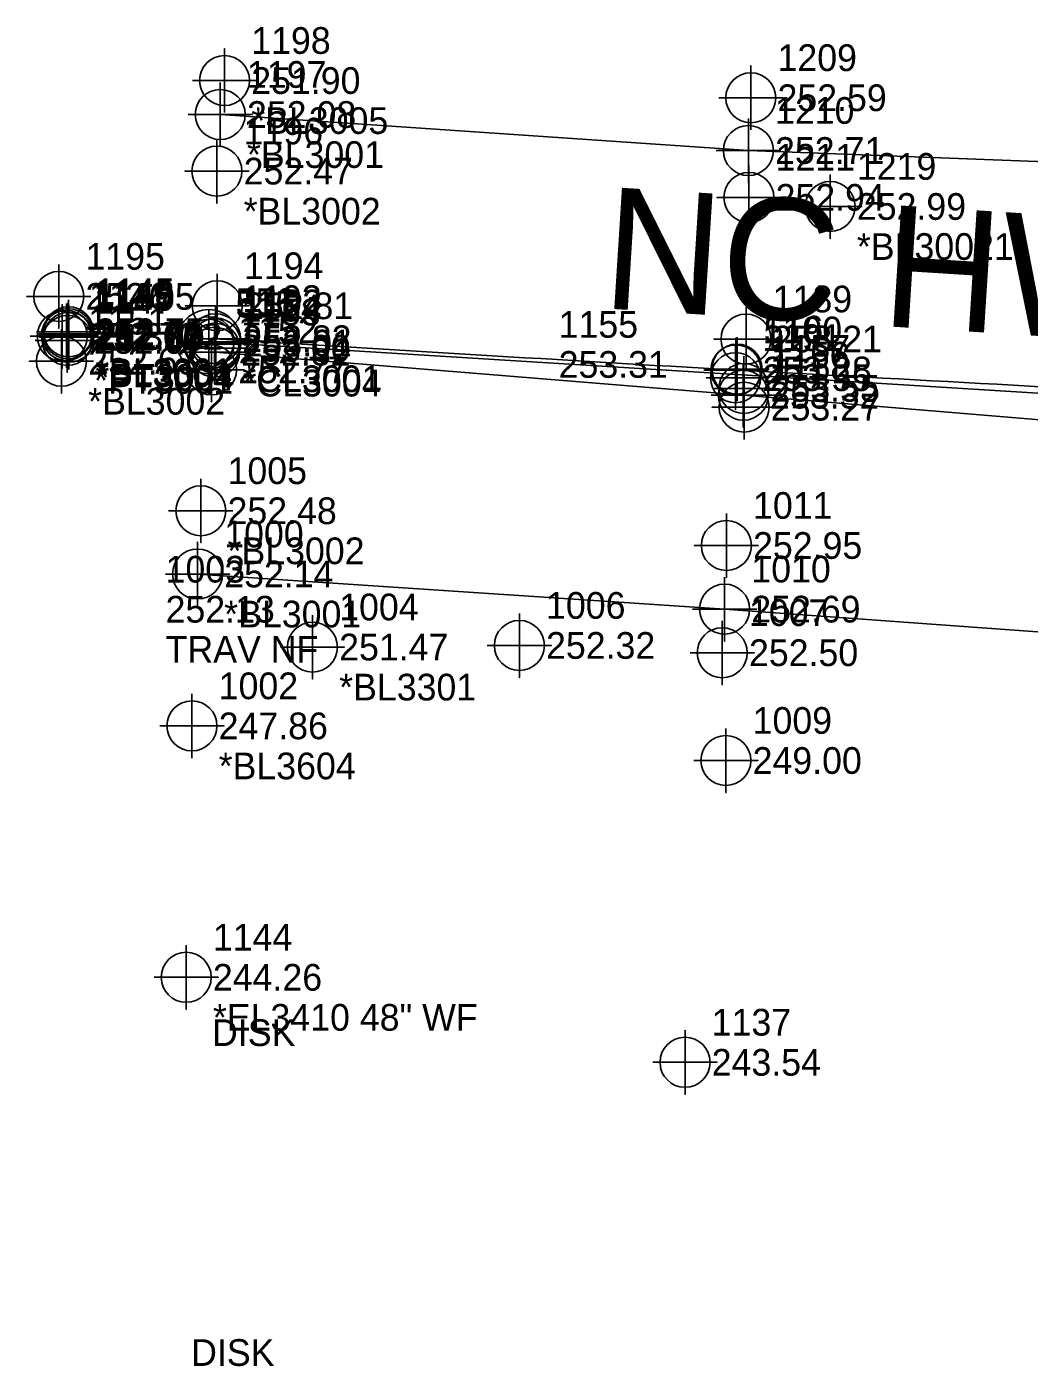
# Model space of a CAD drawing. Extents: x 2130621 to 2131998, y 642516 to 644503.
# Drawn here: x 2130981.3 to 2131075.1, y 643098.3 to 643223.7 of the extents above; entities that cross this region are included whole.
import ezdxf

# ---------------------------------------------------------------- set-up
doc = ezdxf.new("R2010")
doc.units = 0
for name, color, linetype in [('Cogo Default Point CELL', 7, 'Continuous'), ('COGO Default Point Number', 7, 'Continuous'), ('CTL Secondary Horizontal and Vertical Cogo Comment', 7, 'Continuous'), ('CTL Secondary Horizontal and Vertical Cogo Elevation', 7, 'Continuous'), ('CTL Secondary Horizontal and Vertical Cogo Number', 7, 'Continuous'), ('Exist Guardrail Cogo Comment', 7, 'Continuous'), ('Exist Guardrail Cogo Elevation', 7, 'Continuous'), ('Exist Guardrail Cogo Number', 7, 'Continuous'), ('Exist Guardrail Cogo Point CELL', 7, 'Continuous'), ('Exist Other Culture Fence Line Cogo Comment', 7, 'Continuous'), ('Exist Other Culture Fence Line Cogo Elevation', 7, 'Continuous'), ('Exist Other Culture Fence Line Cogo Number', 7, 'Continuous'), ('Exist Other Culture Fence Line Cogo Point CELL', 7, 'Continuous'), ('Exist Other Culture Sign Cogo Elevation', 7, 'Continuous'), ('Exist Other Culture Sign Cogo Number', 7, 'Continuous'), ('Exist Right of Way Monument Cogo Comment', 7, 'Continuous'), ('Exist Roads Curbs Cogo Comment', 7, 'Continuous'), ('Exist Roads Curbs Cogo Elevation', 7, 'Continuous'), ('Exist Roads Curbs Cogo Number', 7, 'Continuous'), ('Exist Roads Curbs Cogo Point CELL', 7, 'Continuous'), ('Exist Roads EOP', 7, 'Continuous'), ('Exist Roads EOP Cogo Comment', 7, 'Continuous'), ('Exist Roads EOP Cogo Elevation', 7, 'Continuous'), ('Exist Roads EOP Cogo Number', 7, 'Continuous'), ('Exist Roads EOP Cogo Point CELL', 7, 'Continuous'), ('Exist Roads EOT Cogo Comment', 7, 'Continuous'), ('Exist Roads EOT Cogo Elevation', 7, 'Continuous'), ('Exist Roads EOT Cogo Number', 7, 'Continuous'), ('Exist Roads EOT Cogo Point CELL', 7, 'Continuous'), ('Exist Roads EOT Text', 7, 'Continuous'), ('Exist Roads Soil Cogo Comment', 7, 'Continuous'), ('Exist Roads Soil Cogo Elevation', 7, 'Continuous'), ('Exist Roads Soil Cogo Number', 7, 'Continuous'), ('Exist Roads Soil Cogo Point CELL', 7, 'Continuous'), ('Exist Vegetation Woods Line Cogo Comment', 7, 'Continuous'), ('Exist Vegetation Woods Line Cogo Elevation', 7, 'Continuous'), ('Exist Vegetation Woods Line Cogo Number', 7, 'Continuous'), ('Exist Vegetation Woods Line Cogo Point CELL', 7, 'Continuous'), ('Prop Horizontal Alignment', 7, 'Continuous')]:
    doc.layers.add(name, color=color, linetype=linetype)

msp = doc.modelspace()

# ---------------------------------------------------------------- linework, layer by layer
at = {"layer": 'Cogo Default Point CELL'}
for points in [[(2130998.32, 643197.18), (2130998.32, 643194.18)], [(2130998.32, 643196.94), (2130998.32, 643193.94)], [(2130995.32, 643194.18), (2130998.32, 643194.18)], [(2130995.32, 643193.94), (2130998.32, 643193.94)], [(2130998.32, 643194.18), (2131001.32, 643194.18)], [(2130998.32, 643194.18), (2130998.32, 643191.18)], [(2130998.32, 643193.94), (2131001.32, 643193.94)], [(2130998.32, 643193.94), (2130998.32, 643190.94)], [(2131047.77, 643194.61), (2131047.77, 643191.61)], [(2131044.77, 643191.61), (2131047.77, 643191.61)], [(2131047.77, 643191.61), (2131050.77, 643191.61)], [(2131047.77, 643191.61), (2131047.77, 643188.61)]]:
    msp.add_lwpolyline(points, dxfattribs=at)
for centre in [(2130998.32, 643194.18), (2130998.32, 643193.94), (2131047.77, 643191.61)]:
    msp.add_circle(centre, 2.34, dxfattribs=at)
at = {"layer": 'Exist Guardrail Cogo Point CELL'}
for points in [[(2131008.02, 643168.59), (2131008.02, 643162.59), (2131008.02, 643165.59), (2131011.02, 643165.59), (2131005.02, 643165.59)], [(2131027.39, 643168.74), (2131027.39, 643162.74), (2131027.39, 643165.74), (2131030.39, 643165.74), (2131024.39, 643165.74)], [(2131046.39, 643168.06), (2131046.39, 643162.06), (2131046.39, 643165.06), (2131049.39, 643165.06), (2131043.39, 643165.06)]]:
    msp.add_lwpolyline(points, dxfattribs=at)
for centre in [(2131008.02, 643165.59), (2131027.39, 643165.74), (2131046.39, 643165.06)]:
    msp.add_circle(centre, 2.34, dxfattribs=at)
at = {"layer": 'Exist Other Culture Fence Line Cogo Point CELL'}
for points in [[(2130996.2, 643137.67), (2130996.2, 643131.67), (2130996.2, 643134.67), (2130999.2, 643134.67), (2130993.2, 643134.67)], [(2131042.9, 643129.71), (2131042.9, 643123.71), (2131042.9, 643126.71), (2131045.9, 643126.71), (2131039.9, 643126.71)]]:
    msp.add_lwpolyline(points, dxfattribs=at)
for centre in [(2130996.2, 643134.67), (2131042.9, 643126.71)]:
    msp.add_circle(centre, 2.34, dxfattribs=at)
at = {"layer": 'Exist Roads Curbs Cogo Point CELL'}
for points in [[(2130984.98, 643197.77), (2130984.98, 643191.77), (2130984.98, 643194.77), (2130982.25, 643194.77), (2130987.98, 643194.77)], [(2130985.16, 643197.92), (2130985.16, 643191.92), (2130985.16, 643194.92), (2130982.43, 643194.92), (2130988.16, 643194.92)], [(2130985.2, 643197.59), (2130985.2, 643191.59), (2130985.2, 643194.59), (2130982.47, 643194.59), (2130988.2, 643194.59)], [(2130998.87, 643196.57), (2130998.87, 643190.57), (2130998.87, 643193.57), (2130996.14, 643193.57), (2131001.87, 643193.57)], [(2130998.98, 643197.05), (2130998.98, 643191.05), (2130998.98, 643194.05), (2130996.25, 643194.05), (2131001.98, 643194.05)], [(2131047.63, 643193.81), (2131047.63, 643187.81), (2131047.63, 643190.81), (2131044.9, 643190.81), (2131050.63, 643190.81)], [(2131048.41, 643192.81), (2131048.41, 643186.81), (2131048.41, 643189.81), (2131045.68, 643189.81), (2131051.41, 643189.81)]]:
    msp.add_lwpolyline(points, dxfattribs=at)
for centre in [(2130984.98, 643194.77), (2130985.16, 643194.92), (2130985.2, 643194.59), (2130998.98, 643194.05), (2130998.87, 643193.57), (2131047.63, 643190.81), (2131048.41, 643189.81)]:
    msp.add_circle(centre, 2.34, dxfattribs=at)
at = {"layer": 'Exist Roads EOP'}
msp.add_line((2130998.95, 643194.46), (2131003.83, 643194.23), dxfattribs=at)
for points in [[(2130999.39, 643215.45), (2131048.83, 643212.08), (2131098.77, 643210.18), (2131123.48, 643210.52)], [(2130999.32, 643193.17), (2131048.36, 643189.17), (2131096.04, 643185.22), (2131148.03, 643181.19), (2131197.86, 643177.88), (2131226.61, 643175.76)], [(2130997.26, 643172.43), (2131046.61, 643169.14), (2131095.28, 643165.62), (2131146.45, 643162.12), (2131188.44, 643158.22), (2131196.4, 643155.89)]]:
    msp.add_lwpolyline(points, dxfattribs=at)
msp.add_spline([(2131226.91, 643179.17), (2131198.07, 643181.47), (2131148.43, 643185.15), (2131096.5, 643188.78), (2131047.67, 643191.53), (2130998.95, 643194.46)], degree=3, dxfattribs=at)
at = {"layer": 'Exist Roads EOP Cogo Point CELL'}
for points in [[(2130999.39, 643218.45), (2130999.39, 643212.45), (2130999.39, 643215.45), (2131002.39, 643215.45), (2130996.39, 643215.45)], [(2131048.83, 643215.08), (2131048.83, 643209.08), (2131048.83, 643212.08), (2131051.83, 643212.08), (2131045.83, 643212.08)], [(2130984.6, 643197.69), (2130984.6, 643191.69), (2130984.6, 643194.69), (2130987.6, 643194.69), (2130981.6, 643194.69)], [(2130985.19, 643198.11), (2130985.19, 643192.11), (2130985.19, 643195.11), (2130988.19, 643195.11), (2130982.19, 643195.11)], [(2130998.95, 643197.46), (2130998.95, 643191.46), (2130998.95, 643194.46), (2131001.95, 643194.46), (2130995.95, 643194.46)], [(2130985.07, 643197.3), (2130985.07, 643191.3), (2130985.07, 643194.3), (2130988.07, 643194.3), (2130982.07, 643194.3)], [(2130998.86, 643196.2), (2130998.86, 643190.2), (2130998.86, 643193.2), (2131001.86, 643193.2), (2130995.86, 643193.2)], [(2131047.67, 643194.53), (2131047.67, 643188.53), (2131047.67, 643191.53), (2131050.67, 643191.53), (2131044.67, 643191.53)], [(2131048.36, 643192.17), (2131048.36, 643186.17), (2131048.36, 643189.17), (2131051.36, 643189.17), (2131045.36, 643189.17)], [(2130997.26, 643175.43), (2130997.26, 643169.43), (2130997.26, 643172.43), (2131000.26, 643172.43), (2130994.26, 643172.43)], [(2131046.61, 643172.14), (2131046.61, 643166.14), (2131046.61, 643169.14), (2131049.61, 643169.14), (2131043.61, 643169.14)]]:
    msp.add_lwpolyline(points, dxfattribs=at)
for centre in [(2130999.39, 643215.45), (2131048.83, 643212.08), (2130985.19, 643195.11), (2130984.6, 643194.69), (2130985.07, 643194.3), (2130998.95, 643194.46), (2130998.86, 643193.2), (2131047.67, 643191.53), (2131048.36, 643189.17), (2130997.26, 643172.43), (2131046.61, 643169.14)]:
    msp.add_circle(centre, 2.34, dxfattribs=at)
at = {"layer": 'Exist Roads EOT Cogo Point CELL'}
for points in [[(2130999.08, 643213.15), (2130999.08, 643207.15), (2130999.08, 643210.15), (2130996.08, 643210.15), (2131002.08, 643210.15)], [(2131048.88, 643210.69), (2131048.88, 643204.69), (2131048.88, 643207.69), (2131045.88, 643207.69), (2131051.88, 643207.69)], [(2131056.49, 643209.84), (2131056.49, 643203.84), (2131056.49, 643206.84), (2131053.49, 643206.84), (2131059.49, 643206.84)], [(2130984.27, 643201.42), (2130984.27, 643195.42), (2130984.27, 643198.42), (2130981.27, 643198.42), (2130987.27, 643198.42)], [(2130999.11, 643200.54), (2130999.11, 643194.54), (2130999.11, 643197.54), (2130996.11, 643197.54), (2131002.11, 643197.54)], [(2131048.61, 643197.43), (2131048.61, 643191.43), (2131048.61, 643194.43), (2131045.61, 643194.43), (2131051.61, 643194.43)], [(2130984.52, 643195.35), (2130984.52, 643189.35), (2130984.52, 643192.35), (2130981.52, 643192.35), (2130987.52, 643192.35)], [(2130998.57, 643194.54), (2130998.57, 643188.54), (2130998.57, 643191.54), (2130995.57, 643191.54), (2131001.57, 643191.54)], [(2131048.43, 643191.05), (2131048.43, 643185.05), (2131048.43, 643188.05), (2131045.43, 643188.05), (2131051.43, 643188.05)], [(2130997.57, 643181.35), (2130997.57, 643175.35), (2130997.57, 643178.35), (2130994.57, 643178.35), (2131000.57, 643178.35)], [(2131046.77, 643178.1), (2131046.77, 643172.1), (2131046.77, 643175.1), (2131043.77, 643175.1), (2131049.77, 643175.1)]]:
    msp.add_lwpolyline(points, dxfattribs=at)
for centre in [(2130999.08, 643210.15), (2131048.88, 643207.69), (2131056.49, 643206.84), (2130984.27, 643198.42), (2130999.11, 643197.54), (2131048.61, 643194.43), (2130984.52, 643192.35), (2130998.57, 643191.54), (2131048.43, 643188.05), (2130997.57, 643178.35), (2131046.77, 643175.1)]:
    msp.add_circle(centre, 2.34, dxfattribs=at)
at = {"layer": 'Exist Roads Soil Cogo Point CELL'}
for points in [[(2130999.79, 643215.63), (2130999.79, 643221.63), (2130999.79, 643218.63), (2131002.79, 643218.63), (2130996.79, 643218.63)], [(2131049.06, 643214.02), (2131049.06, 643220.02), (2131049.06, 643217.02), (2131052.06, 643217.02), (2131046.06, 643217.02)]]:
    msp.add_lwpolyline(points, dxfattribs=at)
for centre in [(2130999.79, 643218.63), (2131049.06, 643217.02)]:
    msp.add_circle(centre, 2.34, dxfattribs=at)
at = {"layer": 'Exist Vegetation Woods Line Cogo Point CELL'}
for points in [[(2130996.74, 643161.21), (2130996.74, 643155.21), (2130996.74, 643158.21), (2130999.74, 643158.21), (2130993.74, 643158.21)], [(2131046.73, 643157.97), (2131046.73, 643151.97), (2131046.73, 643154.97), (2131049.73, 643154.97), (2131043.73, 643154.97)]]:
    msp.add_lwpolyline(points, dxfattribs=at)
for centre in [(2130996.74, 643158.21), (2131046.73, 643154.97)]:
    msp.add_circle(centre, 2.34, dxfattribs=at)
at = {"layer": 'Prop Horizontal Alignment'}
msp.add_line((2130998.32, 643194.18), (2131251.47, 643178.51), dxfattribs=at)
msp.add_circle((2130998.32, 643194.18), 3, dxfattribs=at)

# ---------------------------------------------------------------- texts
at = {"layer": 'COGO Default Point Number'}
for s, p in [('556', (2131000.82, 643196.68)), ('515', (2131000.82, 643196.44)), ('516', (2131050.27, 643194.11))]:
    msp.add_text(s, height=2.5, dxfattribs=at).set_placement(p)
at = {"layer": 'CTL Secondary Horizontal and Vertical Cogo Comment'}
msp.add_text('TRAV NF', height=2.5, dxfattribs=at).set_placement((2130994.27, 643164.13))
at = {"layer": 'CTL Secondary Horizontal and Vertical Cogo Elevation'}
msp.add_text('252.13', height=2.5, dxfattribs=at).set_placement((2130994.27, 643167.88))
at = {"layer": 'CTL Secondary Horizontal and Vertical Cogo Number'}
msp.add_text('1003', height=2.5, dxfattribs=at).set_placement((2130994.27, 643171.63))
at = {"layer": 'Exist Guardrail Cogo Comment'}
msp.add_text('*BL3301', height=2.5, dxfattribs=at).set_placement((2131010.52, 643160.59))
at = {"layer": 'Exist Guardrail Cogo Elevation'}
for s, p in [('251.47', (2131010.52, 643164.34)), ('252.32', (2131029.89, 643164.49)), ('252.50', (2131048.89, 643163.81))]:
    msp.add_text(s, height=2.5, dxfattribs=at).set_placement(p)
at = {"layer": 'Exist Guardrail Cogo Number'}
for s, p in [('1004', (2131010.52, 643168.09)), ('1006', (2131029.89, 643168.24)), ('1007', (2131048.89, 643167.56))]:
    msp.add_text(s, height=2.5, dxfattribs=at).set_placement(p)
at = {"layer": 'Exist Other Culture Fence Line Cogo Comment'}
msp.add_text('*EL3410 48" WF', height=2.5, dxfattribs=at).set_placement((2130998.7, 643129.67))
at = {"layer": 'Exist Other Culture Fence Line Cogo Elevation'}
for s, p in [('244.26', (2130998.7, 643133.42)), ('243.54', (2131045.4, 643125.46))]:
    msp.add_text(s, height=2.5, dxfattribs=at).set_placement(p)
at = {"layer": 'Exist Other Culture Fence Line Cogo Number'}
for s, p in [('1144', (2130998.7, 643137.17)), ('1137', (2131045.4, 643129.21))]:
    msp.add_text(s, height=2.5, dxfattribs=at).set_placement(p)
at = {"layer": 'Exist Other Culture Sign Cogo Elevation'}
msp.add_text('253.31', height=2.5, dxfattribs=at).set_placement((2131031.07, 643190.8))
at = {"layer": 'Exist Other Culture Sign Cogo Number'}
msp.add_text('1155', height=2.5, dxfattribs=at).set_placement((2131031.07, 643194.55))
at = {"layer": 'Exist Right of Way Monument Cogo Comment'}
for p in [(2130998.62, 643128.24), (2130996.66, 643098.29)]:
    msp.add_text('DISK', height=2.5, dxfattribs=at).set_placement(p)
at = {"layer": 'Exist Roads Curbs Cogo Comment'}
for s, p in [('*BL3004', (2130987.66, 643189.92)), ('*PT3004', (2130987.7, 643189.59)), ('*CL3004', (2131001.48, 643189.05))]:
    msp.add_text(s, height=2.5, dxfattribs=at).set_placement(p)
at = {"layer": 'Exist Roads Curbs Cogo Elevation'}
for s, p in [('252.81', (2130987.66, 643193.67)), ('252.78', (2130987.48, 643193.52)), ('252.80', (2130987.7, 643193.34)), ('253.01', (2131001.48, 643192.8)), ('253.00', (2131001.37, 643192.32)), ('253.55', (2131050.13, 643189.56)), ('253.55', (2131050.91, 643188.56))]:
    msp.add_text(s, height=2.5, dxfattribs=at).set_placement(p)
at = {"layer": 'Exist Roads Curbs Cogo Number'}
for s, p in [('1148', (2130987.66, 643197.42)), ('1149', (2130987.48, 643197.27)), ('1150', (2130987.7, 643197.09)), ('1192', (2131001.48, 643196.55)), ('1154', (2131001.37, 643196.07)), ('1191', (2131050.13, 643193.31)), ('1157', (2131050.91, 643192.31))]:
    msp.add_text(s, height=2.5, dxfattribs=at).set_placement(p)
at = {"layer": 'Exist Roads EOP Cogo Comment'}
for s, p in [('*BL3001', (2131001.89, 643210.45)), ('*BL3001', (2130987.69, 643190.11)), ('*PT3001', (2130987.57, 643189.3)), ('*CL3001', (2131001.45, 643189.46)), ('*BL3001', (2130999.76, 643167.43))]:
    msp.add_text(s, height=2.5, dxfattribs=at).set_placement(p)
at = {"layer": 'Exist Roads EOP Cogo Elevation'}
for s, p in [('252.08', (2131001.89, 643214.2)), ('252.71', (2131051.33, 643210.83)), ('252.75', (2130987.69, 643193.86)), ('252.70', (2130987.1, 643193.44)), ('252.67', (2130987.57, 643193.05)), ('252.82', (2131001.45, 643193.21)), ('252.82', (2131001.36, 643191.95)), ('253.28', (2131050.17, 643190.28)), ('253.32', (2131050.86, 643187.92)), ('252.14', (2130999.76, 643171.18)), ('252.69', (2131049.11, 643167.89))]:
    msp.add_text(s, height=2.5, dxfattribs=at).set_placement(p)
at = {"layer": 'Exist Roads EOP Cogo Number'}
for s, p in [('1197', (2131001.89, 643217.95)), ('1210', (2131051.33, 643214.58)), ('1145', (2130987.69, 643197.61)), ('1146', (2130987.1, 643197.19)), ('1147', (2130987.57, 643196.8)), ('1193', (2131001.45, 643196.96)), ('1153', (2131001.36, 643195.7)), ('1190', (2131050.17, 643194.03)), ('1156', (2131050.86, 643191.67)), ('1000', (2130999.76, 643174.93)), ('1010', (2131049.11, 643171.64))]:
    msp.add_text(s, height=2.5, dxfattribs=at).set_placement(p)
at = {"layer": 'Exist Roads EOT Cogo Comment'}
for s, p in [('*BL3002', (2131001.58, 643205.15)), ('*BL30021', (2131058.99, 643201.84)), ('*EL3002', (2130986.77, 643193.42)), ('*BL3002', (2130987.02, 643187.35)), ('*BL3002', (2131000.07, 643173.35))]:
    msp.add_text(s, height=2.5, dxfattribs=at).set_placement(p)
at = {"layer": 'Exist Roads EOT Cogo Elevation'}
for s, p in [('252.47', (2131001.58, 643208.9)), ('252.94', (2131051.38, 643206.44)), ('252.99', (2131058.99, 643205.59)), ('252.65', (2130986.77, 643197.17)), ('252.81', (2131001.61, 643196.29)), ('253.21', (2131051.11, 643193.18)), ('252.63', (2130987.02, 643191.1)), ('252.77', (2131001.07, 643190.29)), ('253.27', (2131050.93, 643186.8)), ('252.48', (2131000.07, 643177.1)), ('252.95', (2131049.27, 643173.85))]:
    msp.add_text(s, height=2.5, dxfattribs=at).set_placement(p)
at = {"layer": 'Exist Roads EOT Cogo Number'}
for s, p in [('1196', (2131001.58, 643212.65)), ('1211', (2131051.38, 643210.19)), ('1219', (2131058.99, 643209.34)), ('1195', (2130986.77, 643200.92)), ('1194', (2131001.61, 643200.04)), ('1189', (2131051.11, 643196.93)), ('1151', (2130987.02, 643194.85)), ('1152', (2131001.07, 643194.04)), ('1158', (2131050.93, 643190.55)), ('1005', (2131000.07, 643180.85)), ('1011', (2131049.27, 643177.6))]:
    msp.add_text(s, height=2.5, dxfattribs=at).set_placement(p)
at = {"layer": 'Exist Roads EOT Text'}
msp.add_text('NC HWY 210 ', height=11.3735, rotation=356.3624, dxfattribs=at).set_placement((2131035.03, 643197.32))
at = {"layer": 'Exist Roads Soil Cogo Comment'}
msp.add_text('*BL3005', height=2.5, dxfattribs=at).set_placement((2131002.29, 643213.63))
at = {"layer": 'Exist Roads Soil Cogo Elevation'}
for s, p in [('251.90', (2131002.29, 643217.38)), ('252.59', (2131051.56, 643215.77))]:
    msp.add_text(s, height=2.5, dxfattribs=at).set_placement(p)
at = {"layer": 'Exist Roads Soil Cogo Number'}
for s, p in [('1198', (2131002.29, 643221.13)), ('1209', (2131051.56, 643219.52))]:
    msp.add_text(s, height=2.5, dxfattribs=at).set_placement(p)
at = {"layer": 'Exist Vegetation Woods Line Cogo Comment'}
msp.add_text('*BL3604', height=2.5, dxfattribs=at).set_placement((2130999.24, 643153.21))
at = {"layer": 'Exist Vegetation Woods Line Cogo Elevation'}
for s, p in [('247.86', (2130999.24, 643156.96)), ('249.00', (2131049.23, 643153.72))]:
    msp.add_text(s, height=2.5, dxfattribs=at).set_placement(p)
at = {"layer": 'Exist Vegetation Woods Line Cogo Number'}
for s, p in [('1002', (2130999.24, 643160.71)), ('1009', (2131049.23, 643157.47))]:
    msp.add_text(s, height=2.5, dxfattribs=at).set_placement(p)

doc.saveas('drawing.dxf')
